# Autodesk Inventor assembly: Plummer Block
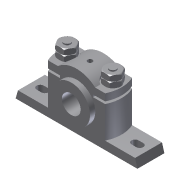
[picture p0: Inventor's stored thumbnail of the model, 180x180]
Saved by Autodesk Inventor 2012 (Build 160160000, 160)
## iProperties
Created: 2011-07
Part Number: Plummer Block
Document SubType Name: Assembly
Designer: CadCim
Author: CadCim
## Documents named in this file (7)
- C:\Users\CadCim\Documents\SAILESH\inventor-2011-fact-prt\c13-inv-2011-prt\c13_inv_2012_prt\Tutorials\c13_tut01_inv\Plummer Block.iam
- C:\Users\CadCim\Documents\SAILESH\inventor-2011-fact-prt\c13-inv-2011-prt\Tutorials\c13-tut01-inv\Casting.ipt
- C:\Users\CadCim\Documents\SAILESH\inventor-2011-fact-prt\c13-inv-2011-prt\Tutorials\c13-tut01-inv\Brasses.ipt
- C:\Users\CadCim\Documents\SAILESH\inventor-2011-fact-prt\c13-inv-2011-prt\Tutorials\c13-tut01-inv\Cap.ipt
- C:\Users\CadCim\Documents\SAILESH\inventor-2011-fact-prt\c13-inv-2011-prt\Tutorials\c13-tut01-inv\Bolt.ipt
- C:\Users\CadCim\Documents\SAILESH\inventor-2011-fact-prt\c13-inv-2011-prt\Tutorials\c13-tut01-inv\Nut.ipt
- C:\Users\CadCim\Documents\SAILESH\inventor-2011-fact-prt\c13-inv-2011-prt\Tutorials\c13-tut01-inv\Lock Nut.ipt
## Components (9 placed, 6 different names)
1. Casting:1 — Mate:1, Mate:2, Insert:1, Insert:2, Angle:1, Angle:2
2. Brasses:1 — Mate:1, Mate:2, Mate:3, Mate:4
3. Cap:1 — Mate:3, Mate:4, Insert:3, Insert:4
4. Bolt:1 — Insert:1, Angle:1
5. Bolt:2 — Insert:2, Angle:2
6. Nut:1 — Insert:3, Insert:6
7. Nut:2 — Insert:4, Insert:5
8. Lock Nut:1 — Insert:6
9. Lock Nut:2 — Insert:5
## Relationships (12: Insert 6, Mate 4, Angle 2)
- Mate:1: Casting:1 ↔ Brasses:1
- Mate:2: Casting:1 ↔ Brasses:1
- Mate:3: Brasses:1 ↔ Cap:1
- Mate:4: Brasses:1 ↔ Cap:1
- Insert:1: Casting:1 ↔ Bolt:1
- Insert:2: Casting:1 ↔ Bolt:2
- Angle:1: Casting:1 ↔ Bolt:1
- Angle:2: Casting:1 ↔ Bolt:2
- Insert:3: Cap:1 ↔ Nut:1
- Insert:4: Cap:1 ↔ Nut:2
- Insert:5: Nut:2 ↔ Lock Nut:2
- Insert:6: Nut:1 ↔ Lock Nut:1
